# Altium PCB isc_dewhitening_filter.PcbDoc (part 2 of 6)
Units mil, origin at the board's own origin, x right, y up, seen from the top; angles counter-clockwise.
Board outline 8440 x 7000 mil, 6 copper layers (Top Layer, MidLayer1, InternalPlane1, Internal Plane 3, InternalPlane2, Bottom Layer); 550 components, 462 nets, 2189 pads, 795 vias.
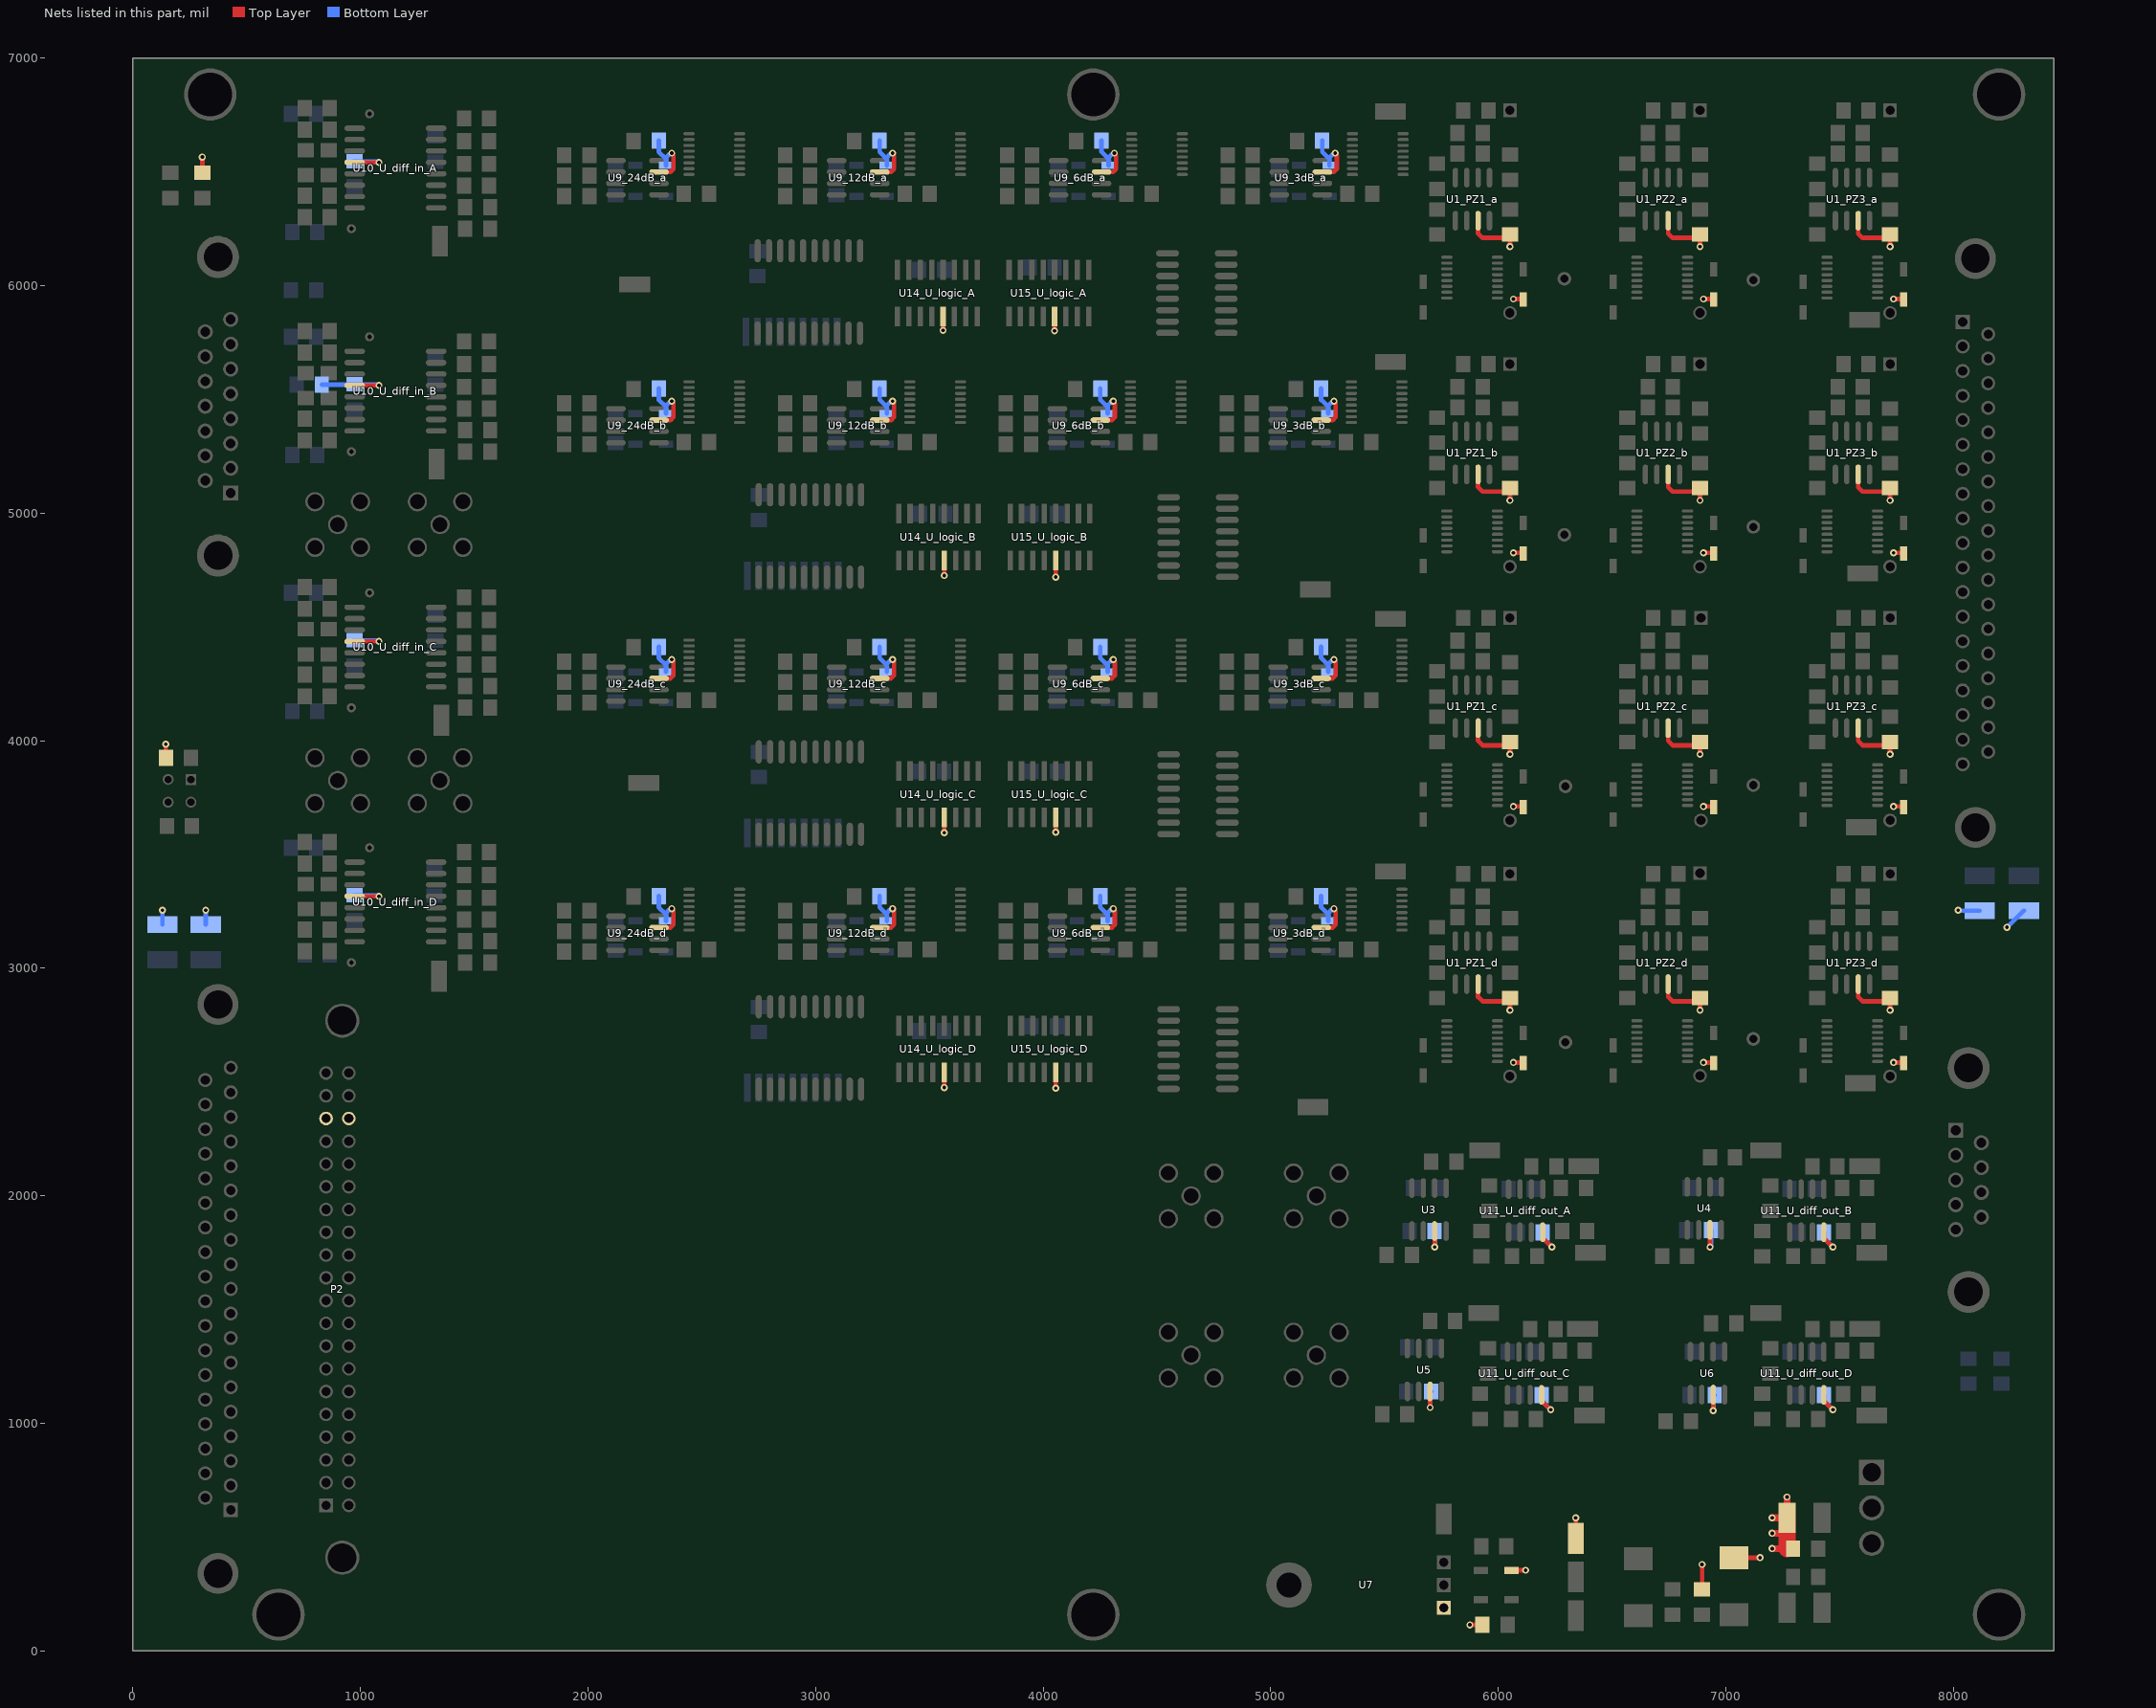
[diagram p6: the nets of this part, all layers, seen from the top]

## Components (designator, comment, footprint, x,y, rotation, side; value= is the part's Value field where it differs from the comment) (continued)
R28_U_diff_out_C "4.99K" 3216[1206] 6110,1020 r0 top (schematic designator R28)
R28_U_diff_out_D "4.99K" 3216[1206] 7350,1020 r0 top (schematic designator R28)
R29_U_logic_A "10K" SRT9 2694.41,5797 r270 bottom (schematic designator R29)
R29_U_logic_B "10K" SRT9 2699.41,4725 r270 bottom (schematic designator R29)
R29_U_logic_C "10K" SRT9 2699.41,3595 r270 bottom (schematic designator R29)
R29_U_logic_D "10K" SRT9 2699.41,2475 r270 bottom (schematic designator R29)
R30_PZ1_a "15K" 3216[1206] 6051,6520 r90 top (schematic designator R30)
R30_PZ1_b "15K" 3216[1206] 6051,5405 r90 top (schematic designator R30)
R30_PZ1_c "15K" 3216[1206] 6051,4290 r90 top (schematic designator R30)
R30_PZ1_d "15K" 3216[1206] 6051,3165 r90 top (schematic designator R30)
R30_PZ2_a "15K" 3216[1206] 6886,6520 r90 top (schematic designator R30)
R30_PZ2_b "15K" 3216[1206] 6886,5405 r90 top (schematic designator R30)
R30_PZ2_c "15K" 3216[1206] 6886,4290 r90 top (schematic designator R30)
R30_PZ2_d "15K" 3216[1206] 6886,3165 r90 top (schematic designator R30)
R30_PZ3_a "15K" 3216[1206] 7721,6520 r90 top (schematic designator R30)
R30_PZ3_b "15K" 3216[1206] 7721,5405 r90 top (schematic designator R30)
R30_PZ3_c "15K" 3216[1206] 7721,4290 r90 top (schematic designator R30)
R30_PZ3_d "15K" 3216[1206] 7721,3165 r90 top (schematic designator R30)
R31_U_logic_A "560" SOP127P760X300-16M 4675,5967 r0 top (schematic designator R31)
R31_U_logic_B "560" SOP127P760X300-16M 4680,4895 r0 top (schematic designator R31)
R31_U_logic_C "560" SOP127P760X300-16M 4680,3765 r0 top (schematic designator R31)
R31_U_logic_D "560" SOP127P760X300-16M 4680,2645 r0 top (schematic designator R31)
R32_U_diff_in_A "1K" 3216[1206] 810,6395 r180 top (schematic designator R32)
R32_U_diff_in_B "1K" 3216[1206] 810,5415 r180 top (schematic designator R32)
R32_U_diff_in_C "1K" 3216[1206] 810,4290 r180 top (schematic designator R32)
R32_U_diff_in_D "1K" 3216[1206] 810,3170 r180 top (schematic designator R32)
R33_U_diff_in_A "1K" 3216[1206] 810,6685 r180 top (schematic designator R33)
R33_U_diff_in_B "1K" 3216[1206] 810,5705 r180 top (schematic designator R33)
R33_U_diff_in_C "1K" 3216[1206] 810,4580 r180 top (schematic designator R33)
R33_U_diff_in_D "1K" 3216[1206] 810,3460 r180 top (schematic designator R33)
R34 "49.9" 3216[1206] 305,6440 r270 bottom
R35 "0" 3216[1206] 775,5565 r0 bottom
R36 "0" 3216[1206] 750,5980 r180 bottom
R37 "49.9" 3216[1206] 8210,1230 r90 bottom
R38 "0" 3216[1206] 7350,450 r180 top
R39 "0" 3216[1206] 7350,325 r180 top
TP1 "TEST POINT" TP_SMT_MICRO 1350,6195 r90 top
TP2 "TEST POINT" TP_SMT_MICRO 5525,6765 r180 top
TP3 "TEST POINT" TP_SMT_MICRO 6340,495 r270 top
TP4 "TEST POINT" TP_SMT_MICRO 6340,325 r270 top
TP5 "TEST POINT" TP_SMT_MICRO 5760,580 r270 top
TP6 "TEST POINT" TP_SMT_MICRO 6340,155 r270 top
TP7_U_diff_out_A "TEST POINT" TP_SMT_MICRO 6375,2130 r180 top (schematic designator TP7)
TP7_U_diff_out_B "TEST POINT" TP_SMT_MICRO 7610,2130 r180 top (schematic designator TP7)
TP7_U_diff_out_C "TEST POINT" TP_SMT_MICRO 6370,1415 r180 top (schematic designator TP7)
TP7_U_diff_out_D "TEST POINT" TP_SMT_MICRO 7610,1415 r180 top (schematic designator TP7)
TP8_U_diff_out_A "TEST POINT" TP_SMT_MICRO 5940,2200 r0 top (schematic designator TP8)
TP8_U_diff_out_B "TEST POINT" TP_SMT_MICRO 7175,2200 r0 top (schematic designator TP8)
TP8_U_diff_out_C "TEST POINT" TP_SMT_MICRO 5935,1485 r0 top (schematic designator TP8)
TP8_U_diff_out_D "TEST POINT" TP_SMT_MICRO 7175,1485 r0 top (schematic designator TP8)
TP9 "TEST POINT" TP_SMT_MICRO 2205,6005 r180 top
TP9_U_diff_out_A "TEST POINT" TP_SMT_MICRO 6405,1750 r0 top (schematic designator TP9)
TP9_U_diff_out_B "TEST POINT" TP_SMT_MICRO 7640,1750 r0 top (schematic designator TP9)
TP9_U_diff_out_C "TEST POINT" TP_SMT_MICRO 6400,1035 r0 top (schematic designator TP9)
TP9_U_diff_out_D "TEST POINT" TP_SMT_MICRO 7640,1035 r0 top (schematic designator TP9)
TP10 "TEST POINT" TP_SMT_MICRO 5195,4665 r0 top
TP11 "TEST POINT" TP_SMT_MICRO 2245,3815 r180 top
TP12 "TEST POINT" TP_SMT_MICRO 5185,2390 r180 top
TP13 "TEST POINT" TP_SMT_MICRO 7610,5850 r180 top
TP14 "TEST POINT" TP_SMT_MICRO 1335,5215 r270 top
TP15 "TEST POINT" TP_SMT_MICRO 5525,5665 r0 top
TP16 "TEST POINT" TP_SMT_MICRO 7600,4735 r0 top
TP17 "TEST POINT" TP_SMT_MICRO 1355,4090 r270 top
TP18 "TEST POINT" TP_SMT_MICRO 5525,4535 r0 top
TP19 "TEST POINT" TP_SMT_MICRO 7595,3620 r180 top
TP20 "TEST POINT" TP_SMT_MICRO 1345,2965 r270 top
TP21 "TEST POINT" TP_SMT_MICRO 5525,3425 r0 top
TP22 "TEST POINT" TP_SMT_MICRO 7590,2495 r180 top
U1_PZ1_a "OP27GS" SOIC127P600-8N 5886,6380 r270 top (schematic designator U1)
U1_PZ1_b "OP27GS" SOIC127P600-8N 5886,5265 r270 top (schematic designator U1)
U1_PZ1_c "OP27GS" SOIC127P600-8N 5886,4150 r270 top (schematic designator U1)
U1_PZ1_d "OP27GS" SOIC127P600-8N 5886,3025 r270 top (schematic designator U1)
U1_PZ2_a "OP27GS" SOIC127P600-8N 6721,6380 r270 top (schematic designator U1)
U1_PZ2_b "OP27GS" SOIC127P600-8N 6721,5265 r270 top (schematic designator U1)
U1_PZ2_c "OP27GS" SOIC127P600-8N 6721,4150 r270 top (schematic designator U1)
U1_PZ2_d "OP27GS" SOIC127P600-8N 6721,3025 r270 top (schematic designator U1)
U1_PZ3_a "OP27GS" SOIC127P600-8N 7556,6380 r270 top (schematic designator U1)
U1_PZ3_b "OP27GS" SOIC127P600-8N 7556,5265 r270 top (schematic designator U1)
U1_PZ3_c "OP27GS" SOIC127P600-8N 7556,4150 r270 top (schematic designator U1)
U1_PZ3_d "OP27GS" SOIC127P600-8N 7556,3025 r270 top (schematic designator U1)
U2_PZ1_a "ADG1436YRUZ-REEL7" ADI-RU-16_L 5885,6035 r0 top (schematic designator U2)
U2_PZ1_b "ADG1436YRUZ-REEL7" ADI-RU-16_L 5885,4920 r0 top (schematic designator U2)
U2_PZ1_c "ADG1436YRUZ-REEL7" ADI-RU-16_L 5885,3805 r0 top (schematic designator U2)
U2_PZ1_d "ADG1436YRUZ-REEL7" ADI-RU-16_L 5885,2680 r0 top (schematic designator U2)
U2_PZ2_a "ADG1436YRUZ-REEL7" ADI-RU-16_L 6720,6035 r0 top (schematic designator U2)
U2_PZ2_b "ADG1436YRUZ-REEL7" ADI-RU-16_L 6720,4920 r0 top (schematic designator U2)
U2_PZ2_c "ADG1436YRUZ-REEL7" ADI-RU-16_L 6720,3805 r0 top (schematic designator U2)
U2_PZ2_d "ADG1436YRUZ-REEL7" ADI-RU-16_L 6720,2680 r0 top (schematic designator U2)
U2_PZ3_a "ADG1436YRUZ-REEL7" ADI-RU-16_L 7555,6035 r0 top (schematic designator U2)
U2_PZ3_b "ADG1436YRUZ-REEL7" ADI-RU-16_L 7555,4920 r0 top (schematic designator U2)
U2_PZ3_c "ADG1436YRUZ-REEL7" ADI-RU-16_L 7555,3805 r0 top (schematic designator U2)
U2_PZ3_d "ADG1436YRUZ-REEL7" ADI-RU-16_L 7555,2680 r0 top (schematic designator U2)
U3 "OP27GS" SOIC127P600-8N 5695,1940 r270 top
U4 "OP27GS" SOIC127P600-8N 6905,1945 r270 top
U5 "OP27GS" SOIC127P600-8N 5675,1235 r270 top
U6 "OP27GS" SOIC127P600-8N 6919,1221 r270 top
U7 "7805C" MY_TO220 5760,290 r90 top
U8_3dB_a "ADG1436YRUZ-REEL7" ADI-RU-16_L 5470,6577.8 r180 top (schematic designator U8)
U8_3dB_b "ADG1436YRUZ-REEL7" ADI-RU-16_L 5465,5487.8 r180 top (schematic designator U8)
U8_3dB_c "ADG1436YRUZ-REEL7" ADI-RU-16_L 5465,4352.8 r180 top (schematic designator U8)
U8_3dB_d "ADG1436YRUZ-REEL7" ADI-RU-16_L 5465,3257.8 r180 top (schematic designator U8)
U8_6dB_a "ADG1436YRUZ-REEL7" ADI-RU-16_L 4500,6577.8 r180 top (schematic designator U8)
U8_6dB_b "ADG1436YRUZ-REEL7" ADI-RU-16_L 4495,5487.8 r180 top (schematic designator U8)
U8_6dB_c "ADG1436YRUZ-REEL7" ADI-RU-16_L 4495,4352.8 r180 top (schematic designator U8)
U8_6dB_d "ADG1436YRUZ-REEL7" ADI-RU-16_L 4495,3257.8 r180 top (schematic designator U8)
U8_12dB_a "ADG1436YRUZ-REEL7" ADI-RU-16_L 3525,6577.8 r180 top (schematic designator U8)
U8_12dB_b "ADG1436YRUZ-REEL7" ADI-RU-16_L 3525,5487.8 r180 top (schematic designator U8)
U8_12dB_c "ADG1436YRUZ-REEL7" ADI-RU-16_L 3525,4352.8 r180 top (schematic designator U8)
U8_12dB_d "ADG1436YRUZ-REEL7" ADI-RU-16_L 3525,3257.8 r180 top (schematic designator U8)
U8_24dB_a "ADG1436YRUZ-REEL7" ADI-RU-16_L 2555,6577.8 r180 top (schematic designator U8)
U8_24dB_b "ADG1436YRUZ-REEL7" ADI-RU-16_L 2555,5487.8 r180 top (schematic designator U8)
U8_24dB_c "ADG1436YRUZ-REEL7" ADI-RU-16_L 2555,4352.8 r180 top (schematic designator U8)
U8_24dB_d "ADG1436YRUZ-REEL7" ADI-RU-16_L 2555,3257.8 r180 top (schematic designator U8)
U9_3dB_a "OP27GS" SOIC127P600-8N 5132,6474 r0 top (schematic designator U9)
U9_3dB_b "OP27GS" SOIC127P600-8N 5127,5384 r0 top (schematic designator U9)
U9_3dB_c "OP27GS" SOIC127P600-8N 5127,4249 r0 top (schematic designator U9)
U9_3dB_d "OP27GS" SOIC127P600-8N 5127,3154 r0 top (schematic designator U9)
U9_6dB_a "OP27GS" SOIC127P600-8N 4162,6474 r0 top (schematic designator U9)
U9_6dB_b "OP27GS" SOIC127P600-8N 4157,5384 r0 top (schematic designator U9)
U9_6dB_c "OP27GS" SOIC127P600-8N 4157,4249 r0 top (schematic designator U9)
U9_6dB_d "OP27GS" SOIC127P600-8N 4157,3154 r0 top (schematic designator U9)
U9_12dB_a "OP27GS" SOIC127P600-8N 3187,6474 r0 top (schematic designator U9)
U9_12dB_b "OP27GS" SOIC127P600-8N 3187,5384 r0 top (schematic designator U9)
U9_12dB_c "OP27GS" SOIC127P600-8N 3187,4249 r0 top (schematic designator U9)
U9_12dB_d "OP27GS" SOIC127P600-8N 3187,3154 r0 top (schematic designator U9)
U9_24dB_a "OP27GS" SOIC127P600-8N 2217,6474 r0 top (schematic designator U9)
U9_24dB_b "OP27GS" SOIC127P600-8N 2217,5384 r0 top (schematic designator U9)
U9_24dB_c "OP27GS" SOIC127P600-8N 2217,4249 r0 top (schematic designator U9)
U9_24dB_d "OP27GS" SOIC127P600-8N 2217,3154 r0 top (schematic designator U9)
U10_U_diff_in_A "LT1125CSW" SOIC127P1030-16N 1153.66,6516.5 r0 top (schematic designator U10)
U10_U_diff_in_B "LT1125CSW" SOIC127P1030-16N 1153.66,5536.5 r0 top (schematic designator U10)
U10_U_diff_in_C "LT1125CSW" SOIC127P1030-16N 1153.66,4411.5 r0 top (schematic designator U10)
U10_U_diff_in_D "LT1125CSW" SOIC127P1030-16N 1153.66,3291.5 r0 top (schematic designator U10)
U11_U_diff_out_A "AD8672ARZ" SOIC127P600-8N 6120,1935 r270 top (schematic designator U11)
U11_U_diff_out_B "AD8672ARZ" SOIC127P600-8N 7355,1935 r270 top (schematic designator U11)
U11_U_diff_out_C "AD8672ARZ" SOIC127P600-8N 6115,1220 r270 top (schematic designator U11)
U11_U_diff_out_D "AD8672ARZ" SOIC127P600-8N 7355,1220 r270 top (schematic designator U11)
U13_U_logic_A "74ALS573" DW020_M 2970,5972 r90 top (schematic designator U13)
U13_U_logic_B "74ALS573" DW020_M 2975,4900 r90 top (schematic designator U13)
U13_U_logic_C "74ALS573" DW020_M 2975,3770 r90 top (schematic designator U13)
U13_U_logic_D "74ALS573" DW020_M 2975,2650 r90 top (schematic designator U13)
U14_U_logic_A "DG412" SOIC16 3535,5967 r180 top (schematic designator U14)
U14_U_logic_B "DG412" SOIC16 3540,4895 r180 top (schematic designator U14)
U14_U_logic_C "DG412" SOIC16 3540,3765 r180 top (schematic designator U14)
U14_U_logic_D "DG412" SOIC16 3540,2645 r180 top (schematic designator U14)
U15_U_logic_A "DG412" SOIC16 4025,5967 r180 top (schematic designator U15)
U15_U_logic_B "DG412" SOIC16 4030,4895 r180 top (schematic designator U15)
U15_U_logic_C "DG412" SOIC16 4030,3765 r180 top (schematic designator U15)
U15_U_logic_D "DG412" SOIC16 4030,2645 r180 top (schematic designator U15)

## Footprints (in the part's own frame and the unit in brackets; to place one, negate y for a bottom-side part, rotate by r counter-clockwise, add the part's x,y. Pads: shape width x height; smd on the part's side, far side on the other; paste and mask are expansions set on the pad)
1812 [mm]
  rect 1.9x3.4 smd: 1(-1.95,0) 2(1.95,0)
  silkscreen extent -0.7,-1.6 0.7,1.6, body extent -2.48,-1.9 2.47,1.91, height 3.42
3216[1206] [mm]
  rect 1.6x1.8 smd: 1(-1.4,0) 2(1.4,0)
  silkscreen extent -0.16,-0.8 0.15,0.79, body extent -1.67,-0.86 1.68,0.87, height 0.85
7343-31 [mil]
  rect 100x125 smd: 1(0,0) 2(-250,0)
  silkscreen extent -290,-85 40,85, body extent -271,-88 21,88
ADI-RU-16_L [mm] "SOP, 16-Leads, Body 5x4.4mm, Pitch 0.65mm, IPC High Density"
  oval 1.25x0.35 smd: 1(-2.825,2.275) 2(-2.825,1.625) 3(-2.825,0.975) 4(-2.825,0.325) 5(-2.825,-0.325) 6(-2.825,-0.975) 7(-2.825,-1.625) 8(-2.825,-2.275) 9(2.825,-2.275) 10(2.825,-1.625) 11(2.825,-0.975) 12(2.825,-0.325) 13(2.825,0.325) 14(2.825,0.975) 15(2.825,1.625) 16(2.825,2.275)
  silkscreen extent -2.95,-2.55 1.8,3.12, body extent -2.25,-2.55 2.25,2.55, height 1.2
DB37/F/RA/125MT [mil]
  rect 62x62 hole 40.5: 1(0,0)
  round 62 hole 40.5: 2(107,0) 3(215,0) 4(324,0) 5(431,0) 6(539,0) 7(647,0) 8(755,0) 9(863,0) 10(971,0) 11(1079,0) 12(1187,0) 13(1295,0) 14(1403,0) 15(1511,0) 16(1619,0) 17(1727,0) 18(1835,0) 19(1943,0) 20(53,112) 21(161,112) 22(269,112) 23(377,112) 24(485,112) 25(593,112) 26(701,112) 27(809,112) 28(917,112) 29(1025,112) 30(1133,112) 31(1241,112) 32(1349,112) 33(1457,112) 34(1565,112) 35(1673,112) 36(1781,112) 37(1889,112)
  round 180 hole 125.9: 38(-279,56) 39(2221,56)
  silkscreen extent -394,-98 2336,666, body extent -402,-72 2336,673, height 497
DSUB1.385-2H9 [mm]
  rect 1.69x1.69 hole 1.097: 1(-5.54,-10.92)
  round 1.69 hole 1.097: 2(-2.77,-10.92) 3(0,-10.92) 4(2.77,-10.92) 5(5.54,-10.92) 6(-4.155,-8.08) 7(-1.385,-8.08) 8(1.385,-8.08) 9(4.155,-8.08)
  round 4.699 hole 3.198: 10(-12.495,-9.5) 11(12.495,-9.5)
  silkscreen extent -15.4,-12.4 15.4,6, body extent -15.49,-12.67 15.49,6.22, height 12.62
DSUB1.385-2H15 [mm]
  rect 1.69x1.69 hole 1.097: 1(-9.695,-10.92)
  round 1.69 hole 1.097: 2(-6.925,-10.92) 3(-4.155,-10.92) 4(-1.385,-10.92) 5(1.385,-10.92) 6(4.155,-10.92) 7(6.925,-10.92) 8(9.695,-10.92) 9(-8.31,-8.08) 10(-5.54,-8.08) 11(-2.77,-8.08) 12(0,-8.08) 13(2.77,-8.08) 14(5.54,-8.08) 15(8.31,-8.08)
  round 4.699 hole 3.198: 16(-16.66,-9.5) 17(16.66,-9.5)
  silkscreen extent -20,-12.5 20,6, body extent -19.68,-12.67 19.69,6.22, height 12.62
DW020_M [mm]
  oval 2.6x0.7 smd: 1(-4.6,5.715) 2(-4.6,4.445) 3(-4.6,3.175) 4(-4.6,1.905) 5(-4.6,0.635) 6(-4.6,-0.635) 7(-4.6,-1.905) 8(-4.6,-3.175) 9(-4.6,-4.445) 10(-4.6,-5.715) 11(4.6,-5.715) 12(4.6,-4.445) 13(4.6,-3.175) 14(4.6,-1.905) 15(4.6,-0.635) 16(4.6,0.635) 17(4.6,1.905) 18(4.6,3.175) 19(4.6,4.445) 20(4.6,5.715)
  silkscreen extent -4.72,-6.5 2.9,6.74, body extent -5.24,-6.42 5.24,6.43, height 2.65
ECQ-E1106KF_Side [mil]
  rect 60x60 hole 40.5: 1(0,0)
  round 60 hole 40.5: 2(890,0)
  silkscreen extent -50,-50 950,340, body extent -62,-688 962,926
Molex_156_RA_3 [mil]
  rect 110x110 hole 80: 1(0,0)
  round 110 hole 80: 2(0,-156) 3(0,-312)
  silkscreen extent 213,-382 792,70, body extent -24,-386 792,76, height 394
"my LUMEX Dual LED" [mil]
  rect 48x48 hole 32: 1(0,0)
  round 48 hole 32: 2(0,-100) 3(-100,0) 4(-100,-100)
  silkscreen extent -320,-140 45,40, body extent -379,-135 45,35, height 380
MY_40-pin_Header_RA [mil]
  rect 60x60 hole 40.5 mask+0: 1(230,-71)
  round 60 hole 40.5 mask+0: 2(230,29) 3(330,-71) 4(330,29) 5(430,-71) 6(430,29) 7(530,-71) 8(530,29) 9(630,-71) 10(630,29) 11(730,-71) 12(730,29) 13(830,-71) 14(830,29) 15(930,-71) 16(930,29) 17(1030,-71) 18(1030,29) 19(1130,-71) 20(1130,29) 21(1230,-71) 22(1230,29) 23(1330,-71) 24(1330,29) 25(1430,-71) 26(1430,29) 27(1530,-71) 28(1530,29) 29(1630,-71) 30(1630,29) 31(1730,-71) 32(1730,29) 33(1830,-71) 34(1830,29) 35(1930,-71) 36(1930,29) 37(2030,-71) 38(2030,29) 39(2130,-71) 40(2130,29)
  round 150 hole 125.9 mask+0: 41(2360,0) 42(0,0)
  silkscreen extent -220,-120 2580,440, body extent -200,-148 2560,978, height 344
MY_TO220 [mil]
  rect 62x62 hole 40.5: 1(-100,0) 2(0,0) 3(100,0)
  round 200 hole 110: 4(0,680)
  silkscreen extent -200,60 200,800, body extent -200,-85 200,795, height 180
SMA [mil] "SMA straight PCB"
  round 85 hole 65: 1(0,0) 2(-100,100) 2(-100,-100) 2(100,100) 2(100,-100)
  silkscreen extent -160,-160 160,160, body extent -126,-126 126,126, height 370
sod123 [mm]
  rect 1.6x0.8 smd: 1(-1.7,0) 2(1.7,0)
  silkscreen extent -1.45,-0.85 1.45,0.85, body extent -1.95,-0.9 1.95,0.9, height 1.18
SOIC16 [mm]
  rect 0.6x2.2 smd: 1(-4.445,-2.6) 2(-3.175,-2.6) 3(-1.905,-2.6) 4(-0.635,-2.6) 5(0.635,-2.6) 6(1.905,-2.6) 7(3.175,-2.6) 8(4.445,-2.6) 9(4.445,2.6) 10(3.175,2.6) 11(1.905,2.6) 12(0.635,2.6) 13(-0.635,2.6) 14(-1.905,2.6) 15(-3.175,2.6) 16(-4.445,2.6)
  silkscreen extent -5.42,-2.72 5,1.1, body extent -4.98,-3.06 4.97,3.06, height 1.75
SOIC127P600-8N [mm]
  oval 2.2x0.6 smd: 1(-2.4,1.905) 2(-2.4,0.635) 3(-2.4,-0.635) 4(-2.4,-1.905) 5(2.4,-1.905) 6(2.4,-0.635) 7(2.4,0.635) 8(2.4,1.905)
  silkscreen extent -2.52,-2.5 0.9,2.88, body extent -3.06,-2.47 3.06,2.48, height 1.75
SOIC127P1030-16N [mm]
  oval 2.3x0.6 smd: 1(-4.55,4.445) 2(-4.55,3.175) 3(-4.55,1.905) 4(-4.55,0.635) 5(-4.55,-0.635) 6(-4.55,-1.905) 7(-4.55,-3.175) 8(-4.55,-4.445) 9(4.55,-4.445) 10(4.55,-3.175) 11(4.55,-1.905) 12(4.55,-0.635) 13(4.55,0.635) 14(4.55,1.905) 15(4.55,3.175) 16(4.55,4.445)
  silkscreen extent -4.67,-5.25 3,5.42, body extent -5.24,-5.18 5.24,5.18, height 2.65
SOP127P760X300-16M [mm]
  oval 2.55x0.7 smd: 1(-3.275,4.445) 2(-3.275,3.175) 3(-3.275,1.905) 4(-3.275,0.635) 5(-3.275,-0.635) 6(-3.275,-1.905) 7(-3.275,-3.175) 8(-3.275,-4.445) 9(3.275,-4.445) 10(3.275,-3.175) 11(3.275,-1.905) 12(3.275,-0.635) 13(3.275,0.635) 14(3.275,1.905) 15(3.275,3.175) 16(3.275,4.445)
  silkscreen extent -3.4,-5.65 1.6,5.65, body extent -3.06,-4.97 3.06,4.98, height 1.75
SRT9 [mil]
  rect 125x30 smd: 1(0,0) 2(0,-50) 3(0,-100) 4(0,-150) 5(0,-200) 6(0,-250) 7(0,-300) 8(0,-350) 9(0,-400)
  silkscreen extent -53,-450 55,52, body extent -40,-450 40,50, height 100
TP_SMT_MICRO [mil]
  rect 135x70 smd: 1(0,0)
  body extent -53,-20 52,20, height 60

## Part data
C1_PZ1_a C1_PZ1_b C1_PZ1_c C1_PZ1_d C1_PZ2_a C1_PZ2_b C1_PZ2_c C1_PZ2_d C1_PZ3_a C1_PZ3_b C1_PZ3_c C1_PZ3_d C3_PZ1_a C3_PZ1_b C3_PZ1_c C3_PZ1_d C3_PZ2_a C3_PZ2_b C3_PZ2_c C3_PZ2_d C3_PZ3_a C3_PZ3_b C3_PZ3_c C3_PZ3_d C6 C8 C9 C11 C12 C14 C15 C17 C19 C22 C24_3dB_a C24_3dB_b C24_3dB_c C24_3dB_d C24_6dB_a C24_6dB_b C24_6dB_c C24_6dB_d C24_12dB_a C24_12dB_b C24_12dB_c C24_12dB_d C24_24dB_a C24_24dB_b C24_24dB_c C24_24dB_d C26_3dB_a C26_3dB_b C26_3dB_c C26_3dB_d C26_6dB_a C26_6dB_b C26_6dB_c C26_6dB_d C26_12dB_a C26_12dB_b C26_12dB_c C26_12dB_d C26_24dB_a C26_24dB_b C26_24dB_c C26_24dB_d C30_U_diff_out_A C30_U_diff_out_B C30_U_diff_out_C C30_U_diff_out_D C31_U_diff_out_A C31_U_diff_out_B C31_U_diff_out_C C31_U_diff_out_D C32_U_logic_A C32_U_logic_B C32_U_logic_C C32_U_logic_D C33_U_logic_A C33_U_logic_B C33_U_logic_C C33_U_logic_D C36_U_logic_A C36_U_logic_B C36_U_logic_C C36_U_logic_D: library part Cap, "Capacitor", Supplier Part Number 1=399-C1206C104K5RACTUCT-ND
C2_PZ1_a C2_PZ1_b C2_PZ1_c C2_PZ1_d C2_PZ2_a C2_PZ2_b C2_PZ2_c C2_PZ2_d C2_PZ3_a C2_PZ3_b C2_PZ3_c C2_PZ3_d C7 C10 C13 C16 C25_3dB_a C25_3dB_b C25_3dB_c C25_3dB_d C25_6dB_a C25_6dB_b C25_6dB_c C25_6dB_d C25_12dB_a C25_12dB_b C25_12dB_c C25_12dB_d C25_24dB_a C25_24dB_b C25_24dB_c C25_24dB_d: library part Cap, "Capacitor", Supplier Part Number 1=399-C1206C680K1HACAUTOCT-ND
C4_PZ1_a C4_PZ1_b C4_PZ1_c C4_PZ1_d C4_PZ2_a C4_PZ2_b C4_PZ2_c C4_PZ2_d C4_PZ3_a C4_PZ3_b C4_PZ3_c C4_PZ3_d C27_3dB_a C27_3dB_b C27_3dB_c C27_3dB_d C27_6dB_a C27_6dB_b C27_6dB_c C27_6dB_d C27_12dB_a C27_12dB_b C27_12dB_c C27_12dB_d C27_24dB_a C27_24dB_b C27_24dB_c C27_24dB_d: library part Cap, "Capacitor"
C5_PZ1_a C5_PZ1_b C5_PZ1_c C5_PZ1_d C5_PZ2_a C5_PZ2_b C5_PZ2_c C5_PZ2_d C5_PZ3_a C5_PZ3_b C5_PZ3_c C5_PZ3_d: library part MYCAP, "Capacitor", Supplier Part Number 1=P14629-ND
C18 C23: library part "CAPACITOR POL", "Polarized Cap", Supplier Part Number 1=478-1722-1-ND
C20 C21 C34 C35: library part MYCAP, "Capacitor", Supplier Part Number 1=1276-1068-1-ND
C28_U_diff_in_A C28_U_diff_in_B C28_U_diff_in_C C28_U_diff_in_D C29_U_diff_in_A C29_U_diff_in_B C29_U_diff_in_C C29_U_diff_in_D: library part MYCAP, "Capacitor", Supplier Part Number 1=1276-3091-1-ND
C37_U_diff_in_A C37_U_diff_in_B C37_U_diff_in_C C37_U_diff_in_D C38_U_diff_in_A C38_U_diff_in_B C38_U_diff_in_C C38_U_diff_in_D C39_U_diff_in_A C39_U_diff_in_B C39_U_diff_in_C C39_U_diff_in_D: library part MYCAP, "Capacitor", Supplier Part Number 1=13-CC1206FRNPO9BN562CT-ND
D1_PZ1_a D1_PZ1_b D1_PZ1_c D1_PZ1_d D1_PZ2_a D1_PZ2_b D1_PZ2_c D1_PZ2_d D1_PZ3_a D1_PZ3_b D1_PZ3_c D1_PZ3_d D2_PZ1_a D2_PZ1_b D2_PZ1_c D2_PZ1_d D2_PZ2_a D2_PZ2_b D2_PZ2_c D2_PZ2_d D2_PZ3_a D2_PZ3_b D2_PZ3_c D2_PZ3_d D3 D5 D6_3dB_a D6_3dB_b D6_3dB_c D6_3dB_d D6_6dB_a D6_6dB_b D6_6dB_c D6_6dB_d D6_12dB_a D6_12dB_b D6_12dB_c D6_12dB_d D6_24dB_a D6_24dB_b D6_24dB_c D6_24dB_d D7_3dB_a D7_3dB_b D7_3dB_c D7_3dB_d D7_6dB_a D7_6dB_b D7_6dB_c D7_6dB_d D7_12dB_a D7_12dB_b D7_12dB_c D7_12dB_d D7_24dB_a D7_24dB_b D7_24dB_c D7_24dB_d: library part Diode, "Diode 1 Amp", Supplier Part Number 1=RB160MM-60CT-ND
D4: library part "Dual Stacked LED", "Dual Green LED", Supplier Part Number 1=67-1321-ND
IN1 IN2 IN3 IN4 OUT1 OUT2 OUT3 OUT4: "SMA, PCB Mount, Right Angle", Supplier Part Number 1=900-0732517040-ND
J5: "15 Position, Right Angle, Receptacle Assembly", Supplier Part Number 1=D15S33E6GX00LF-ND
J6: "9 Position, Right Angle,Receptacle Assembly", Supplier Part Number 1=609-6160-ND
L1 L2: library part INDUCTOR, "INDUCTOR"
L5 L6 L7 L8: library part INDUCTOR, "INDUCTOR", Supplier Part Number 1=CC453232-100KLCT-ND
P1 P3: "Standard D-Subminiature Connector 37 pin", Supplier Part Number 1=D37S33E6GX00LF-ND
P2: "Header, 20-Pin, Dual row, Right Angle", Supplier Part Number 1=609-86130402113345E1LF-ND
P4: "Header, 3-Pin, Right Angle", Supplier Part Number 1=WM5236-ND
R1_PZ1_a R1_PZ1_b R1_PZ1_c R1_PZ1_d R1_PZ2_a R1_PZ2_b R1_PZ2_c R1_PZ2_d R1_PZ3_a R1_PZ3_b R1_PZ3_c R1_PZ3_d R3 R4 R5 R6 R13_3dB_a R13_3dB_b R13_3dB_c R13_3dB_d R13_6dB_a R13_6dB_b R13_6dB_c R13_6dB_d R13_12dB_a R13_12dB_b R13_12dB_c R13_12dB_d R13_24dB_a R13_24dB_b R13_24dB_c R13_24dB_d R17_U_diff_in_A R17_U_diff_in_B R17_U_diff_in_C R17_U_diff_in_D R19_U_diff_in_A R19_U_diff_in_B R19_U_diff_in_C R19_U_diff_in_D R23_U_diff_out_A R23_U_diff_out_B R23_U_diff_out_C R23_U_diff_out_D R26_U_diff_out_A R26_U_diff_out_B R26_U_diff_out_C R26_U_diff_out_D R35 R36 R38 R39: library part Res1, "Resistor", Supplier Part Number 1=HCJ1206ZT0R00CT-ND
R2_PZ1_a R2_PZ1_b R2_PZ1_c R2_PZ1_d R2_PZ2_a R2_PZ2_b R2_PZ2_c R2_PZ2_d R2_PZ3_a R2_PZ3_b R2_PZ3_c R2_PZ3_d: library part Res1, "Resistor", Supplier Part Number 1=P18589CT-ND
R7 R8 R9 R10 R32_U_diff_in_A R32_U_diff_in_B R32_U_diff_in_C R32_U_diff_in_D R33_U_diff_in_A R33_U_diff_in_B R33_U_diff_in_C R33_U_diff_in_D: library part Res1, "Resistor", Supplier Part Number 1=P1.0KBCCT-ND
R11_3dB_a R11_3dB_b R11_3dB_c R11_3dB_d R11_6dB_a R11_6dB_b R11_6dB_c R11_6dB_d R11_12dB_a R11_12dB_b R11_12dB_c R11_12dB_d R11_24dB_a R11_24dB_b R11_24dB_c R11_24dB_d R12_3dB_a R12_3dB_b R12_3dB_c R12_3dB_d R12_6dB_a R12_6dB_b R12_6dB_c R12_6dB_d R12_12dB_a R12_12dB_b R12_12dB_c R12_12dB_d R12_24dB_a R12_24dB_b R12_24dB_c R12_24dB_d R18_U_diff_in_A R18_U_diff_in_B R18_U_diff_in_C R18_U_diff_in_D: library part Res1, "Resistor"
R14_U_diff_in_A R14_U_diff_in_B R14_U_diff_in_C R14_U_diff_in_D R22_U_diff_in_A R22_U_diff_in_B R22_U_diff_in_C R22_U_diff_in_D: library part Res1, "Resistor", Supplier Part Number 1=P1.0MBCCT-ND
R15_U_diff_in_A R15_U_diff_in_B R15_U_diff_in_C R15_U_diff_in_D R16_U_diff_in_A R16_U_diff_in_B R16_U_diff_in_C R16_U_diff_in_D R20_U_diff_in_A R20_U_diff_in_B R20_U_diff_in_C R20_U_diff_in_D R21_U_diff_in_A R21_U_diff_in_B R21_U_diff_in_C R21_U_diff_in_D: library part Res1, "Resistor", Supplier Part Number 1=10-ERA-8AEB302VCT-ND
R24_U_diff_out_A R24_U_diff_out_B R24_U_diff_out_C R24_U_diff_out_D R25_U_diff_out_A R25_U_diff_out_B R25_U_diff_out_C R25_U_diff_out_D R27_U_diff_out_A R27_U_diff_out_B R27_U_diff_out_C R27_U_diff_out_D R28_U_diff_out_A R28_U_diff_out_B R28_U_diff_out_C R28_U_diff_out_D: library part Res1, "Resistor", Supplier Part Number 1=P4.99KBCCT-ND
R29_U_logic_A R29_U_logic_B R29_U_logic_C R29_U_logic_D: library part RES_BUS_8, "8 Bus Resistor", Supplier Part Number 1=60-752091103GPTR7CT-ND
R30_PZ1_a R30_PZ1_b R30_PZ1_c R30_PZ1_d R30_PZ2_a R30_PZ2_b R30_PZ2_c R30_PZ2_d R30_PZ3_a R30_PZ3_b R30_PZ3_c R30_PZ3_d: library part Res1, "Resistor", Supplier Part Number 1=10-ERA-8AEB153VCT-ND
R31_U_logic_A R31_U_logic_B R31_U_logic_C R31_U_logic_D: library part "Res Pack3", "Isolated Resistor Network", Supplier Part Number 1=4816P-1-561LFCT-ND
R34 R37: library part Res1, "Resistor", Supplier Part Number 1=P49.9BCCT-ND
TP1 TP2 TP3 TP4 TP5 TP6 TP7_U_diff_out_A TP7_U_diff_out_B TP7_U_diff_out_C TP7_U_diff_out_D TP8_U_diff_out_A TP8_U_diff_out_B TP8_U_diff_out_C TP8_U_diff_out_D TP9 TP9_U_diff_out_A TP9_U_diff_out_B TP9_U_diff_out_C TP9_U_diff_out_D TP10 TP11 TP12 TP13 TP14 TP15 TP16 TP17 TP18 TP19 TP20 TP21 TP22: library part TESTPT, "PCB Testpoint", Supplier Part Number 1=36-5016CT-ND
U1_PZ1_a U1_PZ1_b U1_PZ1_c U1_PZ1_d U1_PZ2_a U1_PZ2_b U1_PZ2_c U1_PZ2_d U1_PZ3_a U1_PZ3_b U1_PZ3_c U1_PZ3_d U3 U4 U5 U6 U9_3dB_a U9_3dB_b U9_3dB_c U9_3dB_d U9_6dB_a U9_6dB_b U9_6dB_c U9_6dB_d U9_12dB_a U9_12dB_b U9_12dB_c U9_12dB_d U9_24dB_a U9_24dB_b U9_24dB_c U9_24dB_d: library part OP184ES, "Video Operational Amplifier", Supplier Part Number 1=OP27GSZ-REEL7CT-ND
U2_PZ1_a U2_PZ1_b U2_PZ1_c U2_PZ1_d U2_PZ2_a U2_PZ2_b U2_PZ2_c U2_PZ2_d U2_PZ3_a U2_PZ3_b U2_PZ3_c U2_PZ3_d U8_3dB_a U8_3dB_b U8_3dB_c U8_3dB_d U8_6dB_a U8_6dB_b U8_6dB_c U8_6dB_d U8_12dB_a U8_12dB_b U8_12dB_c U8_12dB_d U8_24dB_a U8_24dB_b U8_24dB_c U8_24dB_d: library part CMP-0793-00126-1, "+/-15 V / 12 V / +/-5 V, iCMOS, Dual SPDT Switch, 16-pin SOP (RU-16), Reel"
U7: library part MC7805CD2T, "Three-Terminal Positive Voltage Regulator", Supplier Part Number 1=497-2957-5-ND
U10_U_diff_in_A U10_U_diff_in_B U10_U_diff_in_C U10_U_diff_in_D: library part LT1125CS, "Quad Low Noise, High-Speed Precision Operational Amplifier", Supplier Part Number 1=505-LT1125CSW#PBF-ND
U11_U_diff_out_A U11_U_diff_out_B U11_U_diff_out_C U11_U_diff_out_D: library part AD826AR, "High-Speed, Low-Power Dual Operational Amplifier", Supplier Part Number 1=505-AD8672ARZ-ND
U13_U_logic_A U13_U_logic_B U13_U_logic_C U13_U_logic_D: library part SN74ALS573CDW, "Octal D-Type Transparent Latches with 3-State Outputs", Supplier Part Number 1=296-1129-1-ND
U14_U_logic_A U14_U_logic_B U14_U_logic_C U14_U_logic_D U15_U_logic_A U15_U_logic_B U15_U_logic_C U15_U_logic_D: "Quad Analog SPST NO Switch", Supplier Part Number 1=DG412DY-T1-E3CT-ND

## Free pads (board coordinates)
  round 40 hole 20 mask+0: 0(1040,3530) 0(1040,4650) 0(1040,5775) 0(1040,6755) 1(960,3025) 1(960,4145) 1(960,5270) 1(960,6250)
  round 60 hole 36 mask+0: 0(6290,6030) 1(7120,6025) 2(6290,4905) 3(6295,3800) 4(6295,2675) 5(7120,4940) 6(7120,3805) 7(7120,2690)
  round 230 hole 193: 5(4220,6840) 6(340,6840) 6(640,160) 6(4220,160) 7(8200,160) 8(8200,6840)

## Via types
v1: diameter 31, hole 16, Top Layer to Bottom Layer, 794 vias
v2: diameter 45, hole 20, Top Layer to Bottom Layer, 1 vias

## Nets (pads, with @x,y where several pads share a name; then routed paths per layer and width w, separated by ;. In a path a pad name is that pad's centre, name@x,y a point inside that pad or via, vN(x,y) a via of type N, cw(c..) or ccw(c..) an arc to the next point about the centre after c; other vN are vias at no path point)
+15: C3_PZ1_a.2 C3_PZ1_b.2 C3_PZ1_c.2 C3_PZ1_d.2 C3_PZ2_a.2 C3_PZ2_b.2 C3_PZ2_c.2 C3_PZ2_d.2 C3_PZ3_a.2 C3_PZ3_b.2 C3_PZ3_c.2 C3_PZ3_d.2 C8.2 C11.2 C14.2 C17.2 C18.1 C19.1 C20.2 C26_3dB_a.2 C26_3dB_b.2 C26_3dB_c.2 C26_3dB_d.2 C26_6dB_a.2 C26_6dB_b.2 C26_6dB_c.2 C26_6dB_d.2 C26_12dB_a.2 C26_12dB_b.2 C26_12dB_c.2 C26_12dB_d.2 C26_24dB_a.2 C26_24dB_b.2 C26_24dB_c.2 C26_24dB_d.2 C28_U_diff_in_A.1 C28_U_diff_in_B.1 C28_U_diff_in_C.1 C28_U_diff_in_D.1 C30_U_diff_out_A.1 C30_U_diff_out_B.1 C30_U_diff_out_C.1 C30_U_diff_out_D.1 D2_PZ1_a.1 D2_PZ1_b.1 D2_PZ1_c.1 D2_PZ1_d.1 D2_PZ2_a.1 D2_PZ2_b.1 D2_PZ2_c.1 D2_PZ2_d.1 D2_PZ3_a.1 D2_PZ3_b.1 D2_PZ3_c.1 D2_PZ3_d.1 D3.2 D7_3dB_a.1 D7_3dB_b.1 D7_3dB_c.1 D7_3dB_d.1 D7_6dB_a.1 D7_6dB_b.1 D7_6dB_c.1 D7_6dB_d.1 D7_12dB_a.1 D7_12dB_b.1 D7_12dB_c.1 D7_12dB_d.1 D7_24dB_a.1 D7_24dB_b.1 D7_24dB_c.1 D7_24dB_d.1 L1.2 L5.2 L6.2 L7.2 L8.2 P2.35 P2.36 R7.2 R10.2 R35.2 R38.2 TP3.1 U1_PZ1_a.7 U1_PZ1_b.7 U1_PZ1_c.7 U1_PZ1_d.7 U1_PZ2_a.7 U1_PZ2_b.7 U1_PZ2_c.7 U1_PZ2_d.7 U1_PZ3_a.7 U1_PZ3_b.7 U1_PZ3_c.7 U1_PZ3_d.7 U3.7 U4.7 U5.7 U6.7 U7.1 U9_3dB_a.7 U9_3dB_b.7 U9_3dB_c.7 U9_3dB_d.7 U9_6dB_a.7 U9_6dB_b.7 U9_6dB_c.7 U9_6dB_d.7 U9_12dB_a.7 U9_12dB_b.7 U9_12dB_c.7 U9_12dB_d.7 U9_24dB_a.7 U9_24dB_b.7 U9_24dB_c.7 U9_24dB_d.7 U10_U_diff_in_A.4 U10_U_diff_in_B.4 U10_U_diff_in_C.4 U10_U_diff_in_D.4 U11_U_diff_out_A.8 U11_U_diff_out_B.8 U11_U_diff_out_C.8 U11_U_diff_out_D.8 U14_U_logic_A.13 U14_U_logic_B.13 U14_U_logic_C.13 U14_U_logic_D.13 U15_U_logic_A.13 U15_U_logic_B.13 U15_U_logic_C.13 U15_U_logic_D.13 | length 12760.8
  Top Layer w20: R10.2@144.88,3925 v1(144.88,3984.88) v1@145,3985 ; R7.2@305,6495.12 v1(305,6565) ; U10_U_diff_in_D.4@974.53,3316.5 v1(1081.5,3316.5) ; U10_U_diff_in_C.4@974.53,4436.5 v1(1081.5,4436.5) ; U10_U_diff_in_B.4@974.53,5561.5 v1(1081.5,5561.5) ; U10_U_diff_in_A.4@974.53,6541.5 v1(1081.5,6541.5) ; U9_24dB_d.7@2311.49,3179 2311.55,3179.06 2362.06,3179.06 2375,3192 2375,3252.02 2367.87,3259.16 v1(2367.87,3262.13) ; U9_24dB_c.7@2311.49,4274 2311.55,4274.06 2362.06,4274.06 2375,4287 2375,4347.02 2367.87,4354.16 v1(2367.87,4357.13) ; U9_24dB_b.7@2311.49,5409 2311.55,5409.06 2362.06,5409.06 2375,5422 2375,5482.02 2367.87,5489.16 v1(2367.87,5492.13) ; U9_24dB_a.7@2311.49,6499 2311.55,6499.06 2362.06,6499.06 2375,6512 2375,6572.02 2367.87,6579.16 v1(2367.87,6582.13) ; U9_12dB_d.7@3281.49,3179 3281.55,3179.06 3332.06,3179.06 3345,3192 3345,3252.02 3337.87,3259.16 v1(3337.87,3262.13) ; U9_12dB_c.7@3281.49,4274 3281.55,4274.06 3332.06,4274.06 3345,4287 3345,4347.02 3337.87,4354.16 v1(3337.87,4357.13) ; U9_12dB_b.7@3281.49,5409 3281.55,5409.06 3332.06,5409.06 3345,5422 3345,5482.02 3337.87,5489.16 v1(3337.87,5492.13) ; U9_12dB_a.7@3281.49,6499 3281.55,6499.06 3332.06,6499.06 3345,6512 3345,6572.02 3337.87,6579.16 v1(3337.87,6582.13) ; v1(3560,5803) U14_U_logic_A.13@3560,5864.64 ; v1(3565,2476) U14_U_logic_D.13@3565,2542.64 ; v1(3565,3596) U14_U_logic_C.13@3565,3662.64 ; v1(3565,4726) U14_U_logic_B.13@3565,4792.64 ; v1(4050,5801) U15_U_logic_A.13@4050,5864.64 ; v1(4055,2473) U15_U_logic_D.13@4055,2542.64 ; v1(4055,3598) U15_U_logic_C.13@4055,3662.64 ; v1(4055,4719) U15_U_logic_B.13@4055,4792.64 ; U9_6dB_d.7@4251.49,3179 4251.55,3179.06 4302.06,3179.06 4315,3192 4315,3252.02 4307.87,3259.16 v1(4307.87,3262.13) ; U9_6dB_c.7@4251.49,4274 4251.55,4274.06 4302.06,4274.06 4315,4287 4315,4347.02 4307.87,4354.16 v1(4307.87,4357.13) ; U9_6dB_b.7@4251.49,5409 4251.55,5409.06 4302.06,5409.06 4315,5422 4315,5482.02 4307.87,5489.16 v1(4307.87,5492.13) ; U9_6dB_a.7@4256.49,6499 4256.55,6499.06 4307.06,6499.06 4320,6512 4320,6572.02 4312.87,6579.16 v1(4312.87,6582.13) ; U9_3dB_d.7@5221.49,3179 5221.55,3179.06 5272.06,3179.06 5285,3192 5285,3252.02 5277.87,3259.16 v1(5277.87,3262.13) ; U9_3dB_c.7@5221.49,4274 5221.55,4274.06 5272.06,4274.06 5285,4287 5285,4347.02 5277.87,4354.16 v1(5277.87,4357.13) ; U9_3dB_b.7@5221.49,5409 5221.55,5409.06 5272.06,5409.06 5285,5422 5285,5482.02 5277.87,5489.16 v1(5277.87,5492.13) ; U9_3dB_a.7@5226.49,6499 5226.55,6499.06 5277.06,6499.06 5290,6512 5290,6572.02 5282.87,6579.16 v1(5282.87,6582.13) ; v1(5700,1070) U5.7@5700,1140.51 ; v1(5720,1775) U3.7@5720,1845.51 ; v1(5875,115) C20.2@5929.88,115 ; U1_PZ1_d.7@5911,2930.51 5911,2874 5930,2855 6036.12,2855 C3_PZ1_d.2@6051,2869.88 v1(6051,2816) v1@6050,2815 ; U1_PZ1_c.7@5911,4055.51 5911,3999 5930,3980 6036.12,3980 C3_PZ1_c.2@6051,3994.88 v1(6051,3941) v1@6050,3940 ; U1_PZ1_b.7@5911,5170.51 5911,5114 5930,5095 6036.12,5095 C3_PZ1_b.2@6051,5109.88 v1(6051,5056) v1@6050,5055 ; U1_PZ1_a.7@5911,6285.51 5911,6229 5930,6210 6036.12,6210 C3_PZ1_a.2@6051,6224.88 v1(6051,6171) v1@6050,6170 ; D3.2@6056.93,355 v1(6120,355) ; v1(6066,2586) 6107.07,2586 D2_PZ1_d.1@6110,2583.07 ; v1(6066,3711) 6107.07,3711 D2_PZ1_c.1@6110,3708.07 ; v1(6066,4826) 6107.07,4826 D2_PZ1_b.1@6110,4823.07 ; v1(6066,5941) 6107.07,5941 D2_PZ1_a.1@6110,5938.07 ; U11_U_diff_out_C.8@6190,1125.51 6190,1100 v1(6230,1060) v1@6235,1060 ; U11_U_diff_out_A.8@6195,1840.51 6195,1815 v1(6235,1775) v1@6240,1775 ; TP3.1@6340,495 v1(6340,585) ; U1_PZ2_d.7@6746,2930.51 6746,2874 6765,2855 6871.12,2855 C3_PZ2_d.2@6886,2869.88 v1(6886,2816) v1@6885,2815 ; U1_PZ2_c.7@6746,4055.51 6746,3999 6765,3980 6871.12,3980 C3_PZ2_c.2@6886,3994.88 v1(6886,3941) v1@6885,3940 ; U1_PZ2_b.7@6746,5170.51 6746,5114 6765,5095 6871.12,5095 C3_PZ2_b.2@6886,5109.88 v1(6886,5056) v1@6885,5055 ; U1_PZ2_a.7@6746,6285.51 6746,6229 6765,6210 6871.12,6210 C3_PZ2_a.2@6886,6224.88 v1(6886,6171) v1@6885,6170 ; C19.1@6895,270.12 v1(6895,380) ; v1(6901,2586) 6942.07,2586 D2_PZ2_d.1@6945,2583.07 ; v1(6901,3711) 6942.07,3711 D2_PZ2_c.1@6945,3708.07 ; v1(6901,4826) 6942.07,4826 D2_PZ2_b.1@6945,4823.07 ; v1(6901,5941) 6942.07,5941 D2_PZ2_a.1@6945,5938.07 ; v1@6925,1770 v1(6930,1775) U4.7@6930,1850.51 ; U6.7@6944,1126.51 v1(6944,1056) v1@6945,1055 ; C18.1@7035,410 v1(7150,410) ; U11_U_diff_out_D.8@7430,1125.51 7430,1100 v1(7470,1060) v1@7475,1060 ; U11_U_diff_out_B.8@7430,1840.51 7430,1815 v1(7470,1775) v1@7475,1775 ; U1_PZ3_d.7@7581,2930.51 7581,2874 7600,2855 7706.12,2855 C3_PZ3_d.2@7721,2869.88 v1(7721,2816) v1@7720,2815 ; U1_PZ3_c.7@7581,4055.51 7581,3999 7600,3980 7706.12,3980 C3_PZ3_c.2@7721,3994.88 v1(7721,3941) v1@7720,3940 ; U1_PZ3_b.7@7581,5170.51 7581,5114 7600,5095 7706.12,5095 C3_PZ3_b.2@7721,5109.88 v1(7721,5056) v1@7720,5055 ; U1_PZ3_a.7@7581,6285.51 7581,6229 7600,6210 7706.12,6210 C3_PZ3_a.2@7721,6224.88 v1(7721,6171) v1@7720,6170 ; v1(7736,2586) 7777.07,2586 D2_PZ3_d.1@7780,2583.07 ; v1(7736,3711) 7777.07,3711 D2_PZ3_c.1@7780,3708.07 ; v1(7736,4826) 7777.07,4826 D2_PZ3_b.1@7780,4823.07 ; v1(7736,5941) 7777.07,5941 D2_PZ3_a.1@7780,5938.07
  Top Layer w30: v1(7203.11,450) R38.2@7294.88,450 ; v1(7203.11,517.5) 7268.23,517.5 ; v1(7203.11,585) L1.2@7268.23,585 v1(7268.23,676.77)
  Top Layer w75: R38.2@7268.23,450 L1.2@7268.23,585
  Bottom Layer w20: L5.2@130,3191.77 v1(130,3255) ; L6.2@320,3191.77 v1(320,3255) ; R35.2@830.12,5565 C28_U_diff_in_B.1@972.91,5565 ; C28_U_diff_in_D.1@970,3319.88 v1@1081.5,3319.88 ; C28_U_diff_in_C.1@970,4439.88 v1@1081.5,4439.88 ; C28_U_diff_in_B.1@970,5564.88 v1@1081.5,5564.88 ; C28_U_diff_in_A.1@970,6544.88 v1@1081.5,6544.88 ; C26_24dB_d.2@2311.12,3318 2311.12,3267.88 2342.93,3236.07 ; C26_24dB_c.2@2311.12,4413 2311.12,4362.88 2342.93,4331.07 ; C26_24dB_b.2@2311.12,5548 2311.12,5497.88 2342.93,5466.07 ; C26_24dB_a.2@2311.12,6638 2311.12,6587.88 2342.93,6556.07 ; D7_24dB_d.1@2342.93,3208 2342.93,3242.93 2356.63,3256.63 2359.39,3256.63 2364.89,3262.13 v1(2367.87,3262.13) ; D7_24dB_c.1@2342.93,4303 2342.93,4337.93 2356.63,4351.63 2359.39,4351.63 2364.89,4357.13 v1(2367.87,4357.13) ; D7_24dB_b.1@2342.93,5438 2342.93,5472.93 2356.63,5486.63 2359.39,5486.63 2364.89,5492.13 v1(2367.87,5492.13) ; D7_24dB_a.1@2342.93,6528 2342.93,6562.93 2356.63,6576.63 2359.39,6576.63 2364.89,6582.13 v1(2367.87,6582.13) ; C26_12dB_d.2@3281.12,3318 3281.12,3267.88 3312.93,3236.07 ; C26_12dB_c.2@3281.12,4413 3281.12,4362.88 3312.93,4331.07 ; C26_12dB_b.2@3281.12,5548 3281.12,5497.88 3312.93,5466.07 ; C26_12dB_a.2@3281.12,6638 3281.12,6587.88 3312.93,6556.07 ; D7_12dB_d.1@3312.93,3208 3312.93,3242.93 3326.63,3256.63 3329.39,3256.63 3334.89,3262.13 v1(3337.87,3262.13) ; D7_12dB_c.1@3312.93,4303 3312.93,4337.93 3326.63,4351.63 3329.39,4351.63 3334.89,4357.13 v1(3337.87,4357.13) ; D7_12dB_b.1@3312.93,5438 3312.93,5472.93 3326.63,5486.63 3329.39,5486.63 3334.89,5492.13 v1(3337.87,5492.13) ; D7_12dB_a.1@3312.93,6528 3312.93,6562.93 3326.63,6576.63 3329.39,6576.63 3334.89,6582.13 v1(3337.87,6582.13) ; C26_6dB_d.2@4251.12,3318 4251.12,3267.88 4282.93,3236.07 ; C26_6dB_c.2@4251.12,4413 4251.12,4362.88 4282.93,4331.07 ; C26_6dB_b.2@4251.12,5548 4251.12,5497.88 4282.93,5466.07 ; C26_6dB_a.2@4256.12,6638 4256.12,6587.88 4287.93,6556.07 ; D7_6dB_d.1@4282.93,3208 4282.93,3242.93 4296.63,3256.63 4299.39,3256.63 4304.89,3262.13 v1(4307.87,3262.13) ; D7_6dB_c.1@4282.93,4303 4282.93,4337.93 4296.63,4351.63 4299.39,4351.63 4304.89,4357.13 v1(4307.87,4357.13) ; D7_6dB_b.1@4282.93,5438 4282.93,5472.93 4296.63,5486.63 4299.39,5486.63 4304.89,5492.13 v1(4307.87,5492.13) ; D7_6dB_a.1@4287.93,6528 4287.93,6562.93 4301.63,6576.63 4304.39,6576.63 4309.89,6582.13 v1(4312.87,6582.13) ; C26_3dB_d.2@5221.12,3318 5221.12,3267.88 5252.93,3236.07 ; C26_3dB_c.2@5221.12,4413 5221.12,4362.88 5252.93,4331.07 ; C26_3dB_b.2@5221.12,5548 5221.12,5497.88 5252.93,5466.07 ; C26_3dB_a.2@5226.12,6638 5226.12,6587.88 5257.93,6556.07 ; D7_3dB_d.1@5252.93,3208 5252.93,3242.93 5266.63,3256.63 5269.39,3256.63 5274.89,3262.13 v1(5277.87,3262.13) ; D7_3dB_c.1@5252.93,4303 5252.93,4337.93 5266.63,4351.63 5269.39,4351.63 5274.89,4357.13 v1(5277.87,4357.13) ; D7_3dB_b.1@5252.93,5438 5252.93,5472.93 5266.63,5486.63 5269.39,5486.63 5274.89,5492.13 v1(5277.87,5492.13) ; D7_3dB_a.1@5257.93,6528 5257.93,6562.93 5271.63,6576.63 5274.39,6576.63 5279.89,6582.13 v1(5282.87,6582.13) ; v1(5700,1070) 5700,1134.88 C14.2@5705.12,1140 ; v1(5720,1775) 5720.12,1775.12 C8.2@5720.12,1845 ; C30_U_diff_out_C.1@6190.12,1125 6190.12,1099.88 v1(6230,1060) ; C30_U_diff_out_A.1@6195.12,1840 6195.12,1814.88 v1(6235,1775) ; v1(6930,1775) 6935.12,1780.12 C11.2@6935.12,1850 ; v1(6944,1056) 6944,1118.88 C17.2@6950.12,1125 ; C30_U_diff_out_D.1@7430.12,1125 7430.12,1099.88 v1(7470,1060) ; C30_U_diff_out_B.1@7430.12,1840 7430.12,1814.88 v1(7470,1775) ; v1(8020,3255) 8021.77,3253.23 L8.2@8115,3253.23 ; v1(8235,3180) 8308.23,3253.23 L7.2@8310,3253.23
